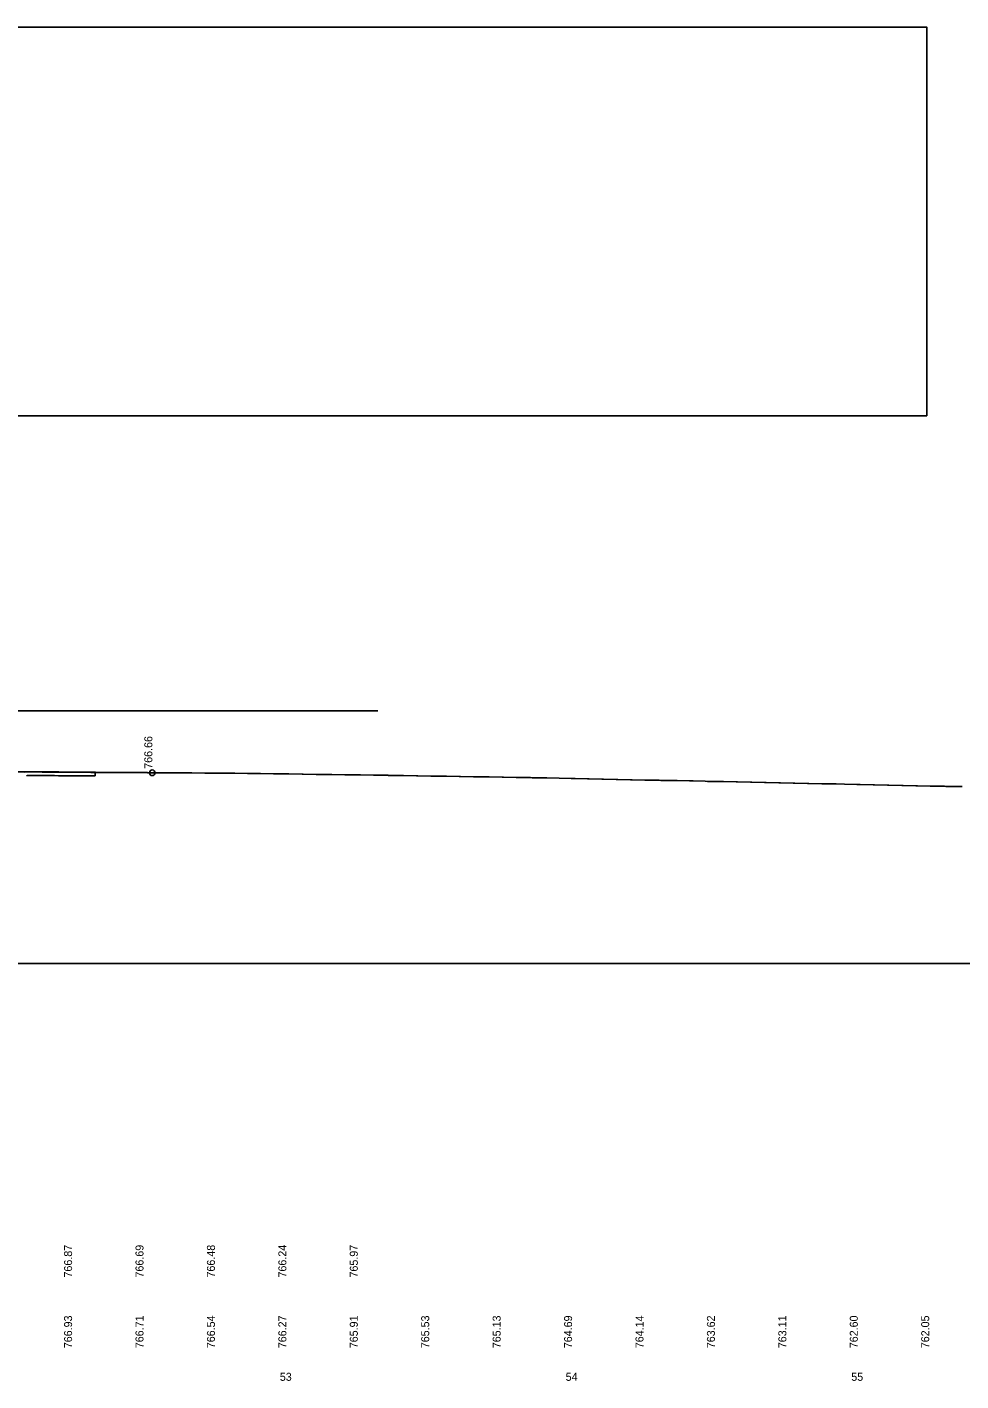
# Model space of a CAD drawing. Extents: x 40 to 3352, y -2509 to 347.
# Drawn here: x 661.7 to 988.5, y -126.3 to 347.3 of the extents above; entities that cross this region are included whole.
import ezdxf

# ---------------------------------------------------------------- set-up
doc = ezdxf.new("R2010")
doc.units = 0
for name, color, linetype in [('BR_P_Gen_Approach_Slab', 7, 'Continuous'), ('Default', 7, 'Continuous'), ('GK_Cells', 7, 'Continuous'), ('PF_P_Grade_Line', 7, 'Continuous'), ('PF_P_Sta_Elev_Text', 7, 'Continuous'), ('PF_P_Text', 7, 'Continuous'), ('PF_X_Ground_Line', 7, 'Continuous'), ('PF_X_Text', 7, 'Continuous')]:
    doc.layers.add(name, color=color, linetype=linetype)

msp = doc.modelspace()

# ---------------------------------------------------------------- linework, layer by layer
at = {"layer": 'BR_P_Gen_Approach_Slab'}
for p, q in [((661.49, 85.3), (661.81, 85.46)), ((685.49, 86.55), (685.49, 85.3))]:
    msp.add_line(p, q, dxfattribs=at)
msp.add_spline([(661.81, 85.46), (671.21, 85.4), (682.53, 85.32), (685.49, 85.3)], degree=3, dxfattribs=at)
at = {"layer": 'Default'}
msp.add_lwpolyline([(88.85, 347.26), (976.56, 347.26), (976.56, 211.32), (88.85, 211.32)], close=True, dxfattribs=at)
at = {"layer": 'GK_Cells'}
msp.add_line((52.42, 19.74), (3352.42, 19.74), dxfattribs=at)
at = {"layer": 'PF_P_Grade_Line'}
msp.add_spline([(299.73, 85.9), (308.97, 85.99), (320.29, 86.11), (331.61, 86.21), (342.93, 86.31), (354.25, 86.4), (365.57, 86.49), (376.89, 86.57), (388.21, 86.65), (399.53, 86.72), (410.85, 86.78), (422.17, 86.84), (433.49, 86.9), (444.81, 86.94), (456.13, 86.98), (467.45, 87.02), (478.77, 87.05), (490.09, 87.07), (501.41, 87.09), (512.73, 87.1), (524.05, 87.11), (535.37, 87.11), (546.69, 87.1), (558.01, 87.09), (569.33, 87.07), (580.65, 87.05), (591.97, 87.02), (603.29, 86.98), (614.61, 86.94), (625.93, 86.9), (637.25, 86.84), (648.57, 86.78), (659.89, 86.72), (671.21, 86.65), (682.53, 86.57), (693.85, 86.49), (705.17, 86.41), (705.49, 86.4)], degree=3, dxfattribs=at)
at = {"layer": 'PF_P_Text'}
msp.add_line((218.41, 108.13), (784.41, 108.13), dxfattribs=at)
msp.add_circle((705.49, 86.4), 1, dxfattribs=at)
at = {"layer": 'PF_X_Ground_Line'}
for points in [[(660.74, 86.67), (663.19, 86.7), (664.53, 86.7), (672.23, 86.68), (672.8, 86.68), (681.68, 86.67), (683.81, 86.63), (685.64, 86.58), (686.73, 86.56), (688.85, 86.54), (689.33, 86.54), (693.85, 86.51), (694.33, 86.51), (698.85, 86.48), (699.33, 86.47), (703.85, 86.44), (704.32, 86.44), (708.85, 86.41), (709.32, 86.4), (713.85, 86.37), (714.32, 86.37), (718.85, 86.34), (719.31, 86.34), (723.85, 86.3), (724.31, 86.3), (728.85, 86.27), (729.31, 86.27), (733.85, 86.24), (734.41, 86.24), (738.82, 86.21), (742.38, 86.16), (742.89, 86.14), (743.35, 86.14), (747.89, 86.07), (748.33, 86.06), (752.89, 86), (753.33, 85.99), (757.89, 85.93), (758.32, 85.92), (762.89, 85.86), (763.32, 85.85), (767.89, 85.79), (768.31, 85.78), (772.89, 85.71), (773.31, 85.71), (777.89, 85.64), (778.31, 85.64), (782.89, 85.57), (783.41, 85.58), (787.88, 85.52), (788.18, 85.51), (792.61, 85.44), (793.39, 85.41), (797.95, 85.34), (798.39, 85.33), (802.94, 85.26), (803.4, 85.25), (807.93, 85.18), (808.4, 85.17), (812.91, 85.1), (813.4, 85.09), (817.9, 85.02), (818.4, 85.01), (822.89, 84.94), (823.41, 84.93), (827.89, 84.86), (828.41, 84.85), (832.88, 84.78), (833.41, 84.77), (837.86, 84.7), (838.43, 84.69), (839.18, 84.69), (843.47, 84.62), (843.6, 84.62), (847.88, 84.53), (852.14, 84.44), (853.44, 84.39), (857.86, 84.3), (858.44, 84.29), (862.86, 84.19), (863.44, 84.18), (867.86, 84.09), (868.44, 84.07), (872.86, 83.98), (873.44, 83.97), (877.86, 83.87), (878.44, 83.86), (882.85, 83.77), (883.43, 83.75), (887.85, 83.66), (888.43, 83.65), (889.19, 83.65), (893.48, 83.56), (894.74, 83.54), (899.04, 83.45), (899.81, 83.41), (900.38, 83.4)], [(900.38, 83.4), (904.81, 83.31), (905.36, 83.3), (909.81, 83.21), (910.36, 83.2), (914.81, 83.1), (915.35, 83.09), (919.81, 83), (920.35, 82.99), (924.81, 82.9), (925.35, 82.89), (929.81, 82.8), (930.33, 82.79), (934.81, 82.69), (935.33, 82.68), (939.81, 82.59), (940.47, 82.59), (944.81, 82.5), (947.77, 82.44), (952.11, 82.35), (952.77, 82.32), (953.29, 82.31), (957.77, 82.21), (958.28, 82.2), (962.77, 82.1), (963.28, 82.09), (967.77, 82), (968.28, 81.99), (972.77, 81.89), (973.28, 81.88), (977.77, 81.78), (978.28, 81.77), (982.77, 81.68), (983.28, 81.66), (987.77, 81.57), (988.28, 81.56), (988.9, 81.56)]]:
    msp.add_lwpolyline(points, dxfattribs=at)

# ---------------------------------------------------------------- texts
at = {"layer": 'PF_P_Sta_Elev_Text'}
for s, p in [('53', (750.12, -126.29)), ('54', (850.17, -126.29)), ('55', (950.13, -126.29))]:
    msp.add_text(s, height=2.8, dxfattribs=at).set_placement(p)
at = {"layer": 'PF_P_Text'}
for s, p in [('766.66', (705.49, 87.8)), ('766.87', (677.41, -90.16)), ('766.69', (702.41, -90.16)), ('766.48', (727.41, -90.16)), ('766.24', (752.41, -90.16)), ('765.97', (777.41, -90.16))]:
    msp.add_text(s, height=2.8, rotation=90, dxfattribs=at).set_placement(p)
at = {"layer": 'PF_X_Text'}
for s, p in [('766.93', (677.41, -114.89)), ('766.71', (702.41, -114.89)), ('766.54', (727.41, -114.89)), ('766.27', (752.41, -114.89)), ('765.91', (777.41, -114.89)), ('765.53', (802.41, -114.89)), ('765.13', (827.41, -114.89)), ('764.69', (852.41, -114.89)), ('764.14', (877.41, -114.89)), ('763.62', (902.41, -114.89)), ('763.11', (927.41, -114.89)), ('762.60', (952.41, -114.89)), ('762.05', (977.41, -114.89))]:
    msp.add_text(s, height=2.8, rotation=90, dxfattribs=at).set_placement(p)

doc.saveas('drawing.dxf')
